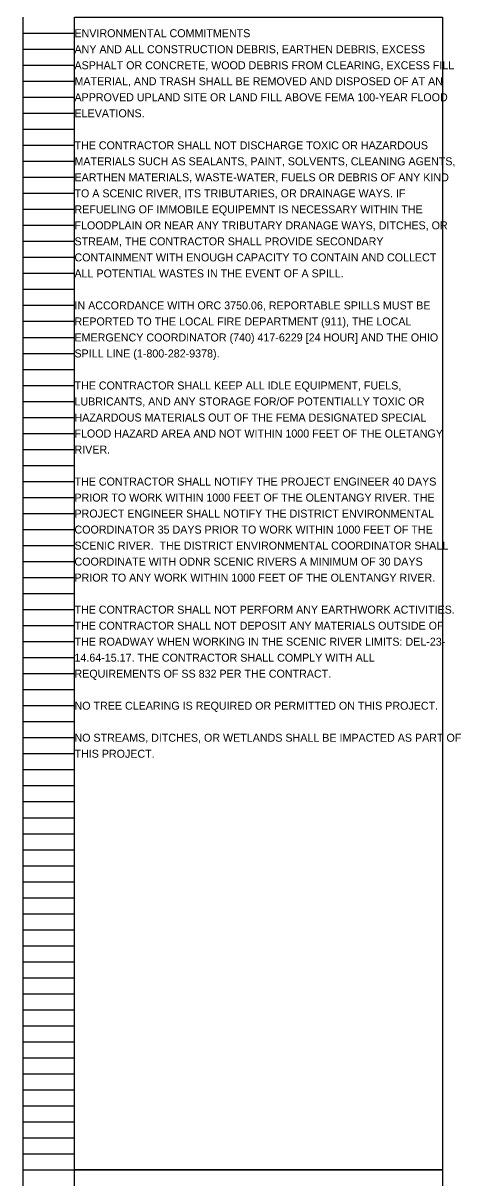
# Model space of a CAD drawing. Extents: x 16463 to 16495, y 5662 to 5823.
# Drawn here: x 16463.05 to 16470.71, y 5722.53 to 5742.73 of the extents above; entities that cross this region are included whole.
import ezdxf

# ---------------------------------------------------------------- set-up
doc = ezdxf.new("R2010")
doc.units = 0
for name, color, linetype in [('Default', 7, 'Continuous'), ('SC_Scratch1', 7, 'Continuous'), ('SH_Data', 7, 'Continuous')]:
    doc.layers.add(name, color=color, linetype=linetype)

msp = doc.modelspace()

# ---------------------------------------------------------------- linework, layer by layer
at = {"layer": 'SC_Scratch1'}
for points in [[(16463.949, 5742.832), (16470.389, 5742.832), (16470.389, 5722.672), (16463.949, 5722.672)], [(16463.949, 5722.672), (16470.389, 5722.672), (16470.389, 5702.512), (16463.949, 5702.512)]]:
    msp.add_lwpolyline(points, close=True, dxfattribs=at)
at = {"layer": 'SH_Data'}
for p, q in [((16463.049, 5722.672), (16463.049, 5742.832)), ((16463.949, 5722.672), (16463.949, 5742.832)), ((16463.049, 5742.552), (16463.949, 5742.552)), ((16463.049, 5742.272), (16463.949, 5742.272)), ((16463.049, 5741.992), (16463.949, 5741.992)), ((16463.049, 5741.712), (16463.949, 5741.712)), ((16463.049, 5741.432), (16463.949, 5741.432)), ((16463.049, 5741.152), (16463.949, 5741.152)), ((16463.049, 5740.872), (16463.949, 5740.872)), ((16463.049, 5740.592), (16463.949, 5740.592)), ((16463.049, 5740.312), (16463.949, 5740.312)), ((16463.049, 5740.032), (16463.949, 5740.032)), ((16463.049, 5739.752), (16463.949, 5739.752)), ((16463.049, 5739.472), (16463.949, 5739.472)), ((16463.049, 5739.192), (16463.949, 5739.192)), ((16463.049, 5738.912), (16463.949, 5738.912)), ((16463.049, 5738.632), (16463.949, 5738.632)), ((16463.049, 5738.352), (16463.949, 5738.352)), ((16463.049, 5738.072), (16463.949, 5738.072)), ((16463.049, 5737.792), (16463.949, 5737.792)), ((16463.049, 5737.512), (16463.949, 5737.512)), ((16463.049, 5737.232), (16463.949, 5737.232)), ((16463.049, 5736.952), (16463.949, 5736.952)), ((16463.049, 5736.672), (16463.949, 5736.672)), ((16463.049, 5736.392), (16463.949, 5736.392)), ((16463.049, 5736.112), (16463.949, 5736.112)), ((16463.049, 5735.832), (16463.949, 5735.832)), ((16463.049, 5735.552), (16463.949, 5735.552)), ((16463.049, 5735.272), (16463.949, 5735.272)), ((16463.049, 5734.992), (16463.949, 5734.992)), ((16463.049, 5734.712), (16463.949, 5734.712)), ((16463.049, 5734.432), (16463.949, 5734.432)), ((16463.049, 5734.152), (16463.949, 5734.152)), ((16463.049, 5733.872), (16463.949, 5733.872)), ((16463.049, 5733.592), (16463.949, 5733.592)), ((16463.049, 5733.312), (16463.949, 5733.312)), ((16463.049, 5733.032), (16463.949, 5733.032)), ((16463.049, 5732.752), (16463.949, 5732.752)), ((16463.049, 5732.472), (16463.949, 5732.472)), ((16463.049, 5732.192), (16463.949, 5732.192)), ((16463.049, 5731.912), (16463.949, 5731.912)), ((16463.049, 5731.632), (16463.949, 5731.632)), ((16463.049, 5731.352), (16463.949, 5731.352)), ((16463.049, 5731.072), (16463.949, 5731.072)), ((16463.049, 5730.792), (16463.949, 5730.792)), ((16463.049, 5730.512), (16463.949, 5730.512)), ((16463.049, 5730.232), (16463.949, 5730.232)), ((16463.049, 5729.952), (16463.949, 5729.952)), ((16463.049, 5729.672), (16463.949, 5729.672)), ((16463.049, 5729.392), (16463.949, 5729.392)), ((16463.049, 5729.112), (16463.949, 5729.112)), ((16463.049, 5728.832), (16463.949, 5728.832)), ((16463.049, 5728.552), (16463.949, 5728.552)), ((16463.049, 5728.272), (16463.949, 5728.272)), ((16463.049, 5727.992), (16463.949, 5727.992)), ((16463.049, 5727.712), (16463.949, 5727.712)), ((16463.049, 5727.432), (16463.949, 5727.432)), ((16463.049, 5727.152), (16463.949, 5727.152)), ((16463.049, 5726.872), (16463.949, 5726.872)), ((16463.049, 5726.592), (16463.949, 5726.592)), ((16463.049, 5726.312), (16463.949, 5726.312)), ((16463.049, 5726.032), (16463.949, 5726.032)), ((16463.049, 5725.752), (16463.949, 5725.752)), ((16463.049, 5725.472), (16463.949, 5725.472)), ((16463.049, 5725.192), (16463.949, 5725.192)), ((16463.049, 5724.912), (16463.949, 5724.912)), ((16463.049, 5724.632), (16463.949, 5724.632)), ((16463.049, 5724.352), (16463.949, 5724.352)), ((16463.049, 5724.072), (16463.949, 5724.072)), ((16463.049, 5723.792), (16463.949, 5723.792)), ((16463.049, 5723.512), (16463.949, 5723.512)), ((16463.049, 5723.232), (16463.949, 5723.232)), ((16463.049, 5722.952), (16463.949, 5722.952)), ((16463.049, 5702.512), (16463.049, 5722.672)), ((16463.049, 5722.672), (16463.949, 5722.672)), ((16463.049, 5722.672), (16463.949, 5722.672)), ((16463.949, 5702.512), (16463.949, 5722.672))]:
    msp.add_line(p, q, dxfattribs=at)

# ---------------------------------------------------------------- texts
at = {"layer": 'Default'}
for s, p in [('ENVIRONMENTAL COMMITMENTS', (16463.949, 5742.48)), ('ANY AND ALL CONSTRUCTION DEBRIS, EARTHEN DEBRIS, EXCESS ', (16463.949, 5742.2)), ('ASPHALT OR CONCRETE, WOOD DEBRIS FROM CLEARING, EXCESS FILL ', (16463.949, 5741.92)), ('MATERIAL, AND TRASH SHALL BE REMOVED AND DISPOSED OF AT AN ', (16463.949, 5741.64)), ('APPROVED UPLAND SITE OR LAND FILL ABOVE FEMA 100-YEAR FLOOD ', (16463.949, 5741.36)), ('ELEVATIONS.', (16463.949, 5741.08)), ('THE CONTRACTOR SHALL NOT DISCHARGE TOXIC OR HAZARDOUS ', (16463.949, 5740.52)), ('MATERIALS SUCH AS SEALANTS, PAINT, SOLVENTS, CLEANING AGENTS, ', (16463.949, 5740.24)), ('EARTHEN MATERIALS, WASTE-WATER, FUELS OR DEBRIS OF ANY KIND ', (16463.949, 5739.96)), ('TO A SCENIC RIVER, ITS TRIBUTARIES, OR DRAINAGE WAYS. IF ', (16463.949, 5739.68)), ('REFUELING OF IMMOBILE EQUIPEMNT IS NECESSARY WITHIN THE ', (16463.949, 5739.4)), ('FLOODPLAIN OR NEAR ANY TRIBUTARY DRANAGE WAYS, DITCHES, OR ', (16463.949, 5739.12)), ('STREAM, THE CONTRACTOR SHALL PROVIDE SECONDARY ', (16463.949, 5738.84)), ('CONTAINMENT WITH ENOUGH CAPACITY TO CONTAIN AND COLLECT ', (16463.949, 5738.56)), ('ALL POTENTIAL WASTES IN THE EVENT OF A SPILL.', (16463.949, 5738.28)), ('IN ACCORDANCE WITH ORC 3750.06, REPORTABLE SPILLS MUST BE ', (16463.949, 5737.72)), ('REPORTED TO THE LOCAL FIRE DEPARTMENT (911), THE LOCAL ', (16463.949, 5737.44)), ('EMERGENCY COORDINATOR (740) 417-6229 [24 HOUR] AND THE OHIO ', (16463.949, 5737.16)), ('SPILL LINE (1-800-282-9378).', (16463.949, 5736.88)), ('THE CONTRACTOR SHALL KEEP ALL IDLE EQUIPMENT, FUELS, ', (16463.949, 5736.32)), ('LUBRICANTS, AND ANY STORAGE FOR/OF POTENTIALLY TOXIC OR ', (16463.949, 5736.04)), ('HAZARDOUS MATERIALS OUT OF THE FEMA DESIGNATED SPECIAL ', (16463.949, 5735.76)), ('FLOOD HAZARD AREA AND NOT WITHIN 1000 FEET OF THE OLETANGY ', (16463.949, 5735.48)), ('RIVER.', (16463.949, 5735.2)), ('THE CONTRACTOR SHALL NOTIFY THE PROJECT ENGINEER 40 DAYS ', (16463.949, 5734.64)), ('PRIOR TO WORK WITHIN 1000 FEET OF THE OLENTANGY RIVER. THE ', (16463.949, 5734.36)), ('PROJECT ENGINEER SHALL NOTIFY THE DISTRICT ENVIRONMENTAL ', (16463.949, 5734.08)), ('COORDINATOR 35 DAYS PRIOR TO WORK WITHIN 1000 FEET OF THE ', (16463.949, 5733.8)), ('SCENIC RIVER.  THE DISTRICT ENVIRONMENTAL COORDINATOR SHALL ', (16463.949, 5733.52)), ('COORDINATE WITH ODNR SCENIC RIVERS A MINIMUM OF 30 DAYS ', (16463.949, 5733.24)), ('PRIOR TO ANY WORK WITHIN 1000 FEET OF THE OLENTANGY RIVER. ', (16463.949, 5732.96)), ('THE CONTRACTOR SHALL NOT PERFORM ANY EARTHWORK ACTIVITIES. ', (16463.949, 5732.4)), ('THE CONTRACTOR SHALL NOT DEPOSIT ANY MATERIALS OUTSIDE OF ', (16463.949, 5732.12)), ('THE ROADWAY WHEN WORKING IN THE SCENIC RIVER LIMITS: DEL-23-', (16463.949, 5731.84)), ('14.64-15.17. THE CONTRACTOR SHALL COMPLY WITH ALL ', (16463.949, 5731.56)), ('REQUIREMENTS OF SS 832 PER THE CONTRACT.', (16463.949, 5731.28)), ('NO TREE CLEARING IS REQUIRED OR PERMITTED ON THIS PROJECT.', (16463.949, 5730.72)), ('NO STREAMS, DITCHES, OR WETLANDS SHALL BE IMPACTED AS PART OF ', (16463.949, 5730.16)), ('THIS PROJECT.', (16463.949, 5729.88))]:
    msp.add_text(s, height=0.14, dxfattribs=at).set_placement(p)

doc.saveas('drawing.dxf')
